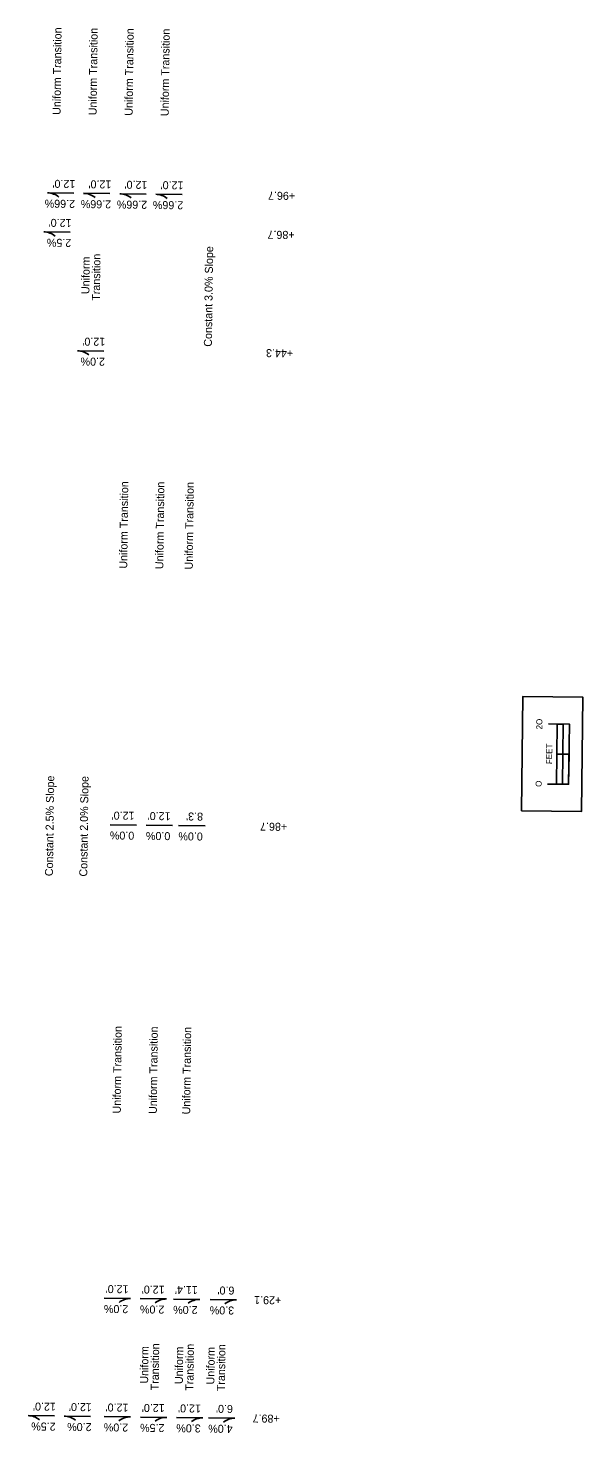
# Model space of a CAD drawing. Extents: x 20505303 to 20506906, y 7965397 to 7979025.
# Drawn here: x 20506721.2 to 20506905.8, y 7972885 to 7973352.6 of the extents above; entities that cross this region are included whole.
import ezdxf

# ---------------------------------------------------------------- set-up
doc = ezdxf.new("R2010")
doc.units = 0
doc.layers.add('Alignment', color=7, linetype='Continuous')

msp = doc.modelspace()

# ---------------------------------------------------------------- linework, layer by layer
at = {"layer": 'Alignment'}
for p, q in [((20506736.45, 7973297.6), (20506727.68, 7973297.71)), ((20506748.45, 7973297.45), (20506739.68, 7973297.56)), ((20506760.45, 7973297.29), (20506751.68, 7973297.4)), ((20506772.45, 7973297.14), (20506763.68, 7973297.25)), ((20506735.18, 7973284.61), (20506726.41, 7973284.72)), ((20506746.4, 7973245.07), (20506737.63, 7973245.18)), ((20506901.21, 7973110.89), (20506897.21, 7973110.94)), ((20506901.21, 7973110.89), (20506897.21, 7973110.94)), ((20506748.51, 7973087.43), (20506757.28, 7973087.32)), ((20506760.51, 7973087.28), (20506769.28, 7973087.17)), ((20506771.31, 7973087.14), (20506780.08, 7973087.03)), ((20506746.53, 7972929.84), (20506755.3, 7972929.73)), ((20506758.53, 7972929.69), (20506767.3, 7972929.58)), ((20506769.58, 7972929.55), (20506778.35, 7972929.44)), ((20506781.75, 7972929.4), (20506790.52, 7972929.29)), ((20506729.98, 7972890.65), (20506721.21, 7972890.76)), ((20506741.94, 7972890.5), (20506733.17, 7972890.61)), ((20506746.5, 7972890.44), (20506755.27, 7972890.33)), ((20506758.56, 7972890.29), (20506767.33, 7972890.18)), ((20506770.62, 7972890.14), (20506779.39, 7972890.03)), ((20506781.25, 7972890), (20506790.03, 7972889.89))]:
    msp.add_line(p, q, dxfattribs=at)
for points in [[(20506885.38, 7973092.08), (20506885.83, 7973130.07), (20506905.83, 7973129.84), (20506905.38, 7973091.84)], [(20506885.38, 7973092.08), (20506885.83, 7973130.07), (20506905.83, 7973129.84), (20506905.38, 7973091.84)], [(20506899.19, 7973110.91), (20506899.31, 7973120.91), (20506897.32, 7973120.94), (20506897.21, 7973110.94)], [(20506901.09, 7973100.89), (20506901.21, 7973110.89), (20506899.19, 7973110.91), (20506899.07, 7973100.91)]]:
    msp.add_lwpolyline(points, close=True, dxfattribs=at)
for points in [[(20506894.09, 7973100.97), (20506901.09, 7973100.89), (20506901.32, 7973120.89), (20506894.33, 7973120.97)], [(20506897.09, 7973100.94), (20506897.32, 7973120.94)]]:
    msp.add_lwpolyline(points, dxfattribs=at)
for centre, start, end in [((20506727.6, 7973291.54), 51.076, 89.2791), ((20506739.6, 7973291.39), 51.076, 89.2791), ((20506751.6, 7973291.24), 51.076, 89.2791), ((20506763.6, 7973291.09), 51.076, 89.2791), ((20506726.34, 7973278.56), 51.076, 89.2791), ((20506737.56, 7973239.02), 51.076, 89.2791), ((20506755.22, 7972923.57), 89.2791, 127.4821), ((20506767.22, 7972923.42), 89.2791, 127.4821), ((20506778.27, 7972923.28), 89.2791, 127.4821), ((20506790.44, 7972923.12), 89.2791, 127.4821), ((20506721.13, 7972884.59), 51.076, 89.2791), ((20506733.09, 7972884.44), 51.076, 89.2791), ((20506755.19, 7972884.17), 89.2791, 127.4821), ((20506767.25, 7972884.01), 89.2791, 127.4821), ((20506779.31, 7972883.86), 89.2791, 127.4821), ((20506789.95, 7972883.73), 89.2791, 127.4821)]:
    msp.add_arc(centre, 6.16, start, end, dxfattribs=at)

# ---------------------------------------------------------------- texts
for s, height, rotation, p in [('Uniform Transition', 2.664, 89.2905, (20506732, 7973323.66)), ('Uniform Transition', 2.664, 89.2905, (20506744, 7973323.52)), ('Uniform Transition', 2.664, 89.2905, (20506755.99, 7973323.38)), ('Uniform Transition', 2.664, 89.2905, (20506767.99, 7973323.23)), ("12.0'", 2.664, 179.3818, (20506736.94, 7973301.99)), ("12.0'", 2.664, 179.3818, (20506748.93, 7973301.83)), ("12.0'", 2.664, 179.3818, (20506760.93, 7973301.68)), ("12.0'", 2.664, 179.3818, (20506772.93, 7973301.53)), ('+96.7', 2.664, 179.3818, (20506810.08, 7973298.01)), ('2.66%', 2.664, 179.3818, (20506736.85, 7973295.36)), ('2.66%', 2.664, 179.3818, (20506748.85, 7973295.21)), ('2.66%', 2.664, 179.3818, (20506760.85, 7973295.06)), ('2.66%', 2.664, 179.3818, (20506772.85, 7973294.91)), ("12.0'", 2.664, 179.3818, (20506735.67, 7973289)), ('+86.7', 2.664, 179.3818, (20506809.91, 7973285.02)), ('2.5%', 2.664, 179.3818, (20506735.58, 7973282.38)), ('Constant 3.0% Slope', 2.664, 89.2393, (20506782.36, 7973246.49)), ('Uniform', 2.664, 89.2905, (20506741.59, 7973264.02)), ('Transition', 2.664, 89.2905, (20506745.1, 7973261.79)), ("12.0'", 2.664, 179.3818, (20506746.89, 7973249.46)), ('+44.3', 2.664, 179.3818, (20506809.42, 7973245.62)), ('2.0%', 2.664, 179.3818, (20506746.8, 7973242.83)), ('Uniform Transition', 2.664, 89.2905, (20506754.2, 7973172.63)), ('Uniform Transition', 2.664, 89.2905, (20506766.2, 7973172.48)), ('Uniform Transition', 2.664, 89.2905, (20506775.99, 7973172.36)), ('2O', 2, 89.3168, (20506892.3, 7973119.12)), ('FEET', 2, 89.3168, (20506895.56, 7973107.57)), ('Constant 2.5% Slope', 2.664, 89.2393, (20506729.47, 7973070.29)), ('Constant 2.0% Slope', 2.664, 89.2393, (20506740.89, 7973070.15)), ('O', 2, 89.3168, (20506892.07, 7973100.01)), ("12.0'", 2.664, 179.3818, (20506756.63, 7973091.72)), ("12.0'", 2.664, 179.3818, (20506768.63, 7973091.57)), ("8.3'", 2.664, 179.3818, (20506779.43, 7973091.44)), ('+86.7', 2.664, 179.3818, (20506807.43, 7973088.03)), ('0.0%', 2.664, 179.3818, (20506756.55, 7973085.1)), ('0.0%', 2.664, 179.3818, (20506768.55, 7973084.95)), ('0.0%', 2.664, 179.3818, (20506779.35, 7973084.81)), ('Uniform Transition', 2.664, 89.2905, (20506752.03, 7972991.3)), ('Uniform Transition', 2.664, 89.2905, (20506764.03, 7972991.15)), ('Uniform Transition', 2.664, 89.2905, (20506775.13, 7972991.01)), ("12.0'", 2.664, 179.3818, (20506754.65, 7972934.14)), ("12.0'", 2.664, 179.3818, (20506766.65, 7972933.98)), ("11.4'", 2.664, 179.3818, (20506777.7, 7972933.85)), ("6.0'", 2.664, 179.3818, (20506789.88, 7972933.69)), ('2.0%', 2.664, 179.3818, (20506754.57, 7972927.51)), ('2.0%', 2.664, 179.3818, (20506766.56, 7972927.36)), ('2.0%', 2.664, 179.3818, (20506777.62, 7972927.22)), ('+29.1', 2.664, 179.3818, (20506805.47, 7972930.44)), ('3.0%', 2.664, 179.3818, (20506789.79, 7972927.07)), ('Uniform', 2.664, 89.2905, (20506761.13, 7972901.39)), ('Transition', 2.664, 89.2905, (20506764.65, 7972899.16)), ('Uniform', 2.664, 89.2905, (20506772.69, 7972901.25)), ('Transition', 2.664, 89.2905, (20506776.21, 7972899.01)), ('Uniform', 2.664, 89.2905, (20506783.18, 7972901.11)), ('Transition', 2.664, 89.2905, (20506786.69, 7972898.88)), ("12.0'", 2.664, 179.3818, (20506730.46, 7972895.04)), ("12.0'", 2.664, 179.3818, (20506742.43, 7972894.89)), ("12.0'", 2.664, 179.3818, (20506754.62, 7972894.73)), ("12.0'", 2.664, 179.3818, (20506766.68, 7972894.58)), ("12.0'", 2.664, 179.3818, (20506778.74, 7972894.43)), ("6.0'", 2.664, 179.3818, (20506789.38, 7972894.3)), ('+89.7', 2.664, 179.3818, (20506804.95, 7972891.05)), ('2.5%', 2.664, 179.3818, (20506730.38, 7972888.41)), ('2.0%', 2.664, 179.3818, (20506742.34, 7972888.26)), ('2.0%', 2.664, 179.3818, (20506754.53, 7972888.11)), ('2.5%', 2.664, 179.3818, (20506766.6, 7972887.96)), ('3.0%', 2.664, 179.3818, (20506778.66, 7972887.81)), ('4.0%', 2.664, 179.3818, (20506789.29, 7972887.67))]:
    msp.add_text(s, height=height, rotation=rotation, dxfattribs=at).set_placement(p)

doc.saveas('drawing.dxf')
